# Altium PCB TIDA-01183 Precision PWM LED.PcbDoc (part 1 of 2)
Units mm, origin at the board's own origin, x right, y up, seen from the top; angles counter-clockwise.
Board outline 88 x 70 mm, 2 copper layers (Top Layer, Bottom Layer), stack 1.575 mm thick; 108 components, 41 nets, 240 pads, 138 vias.
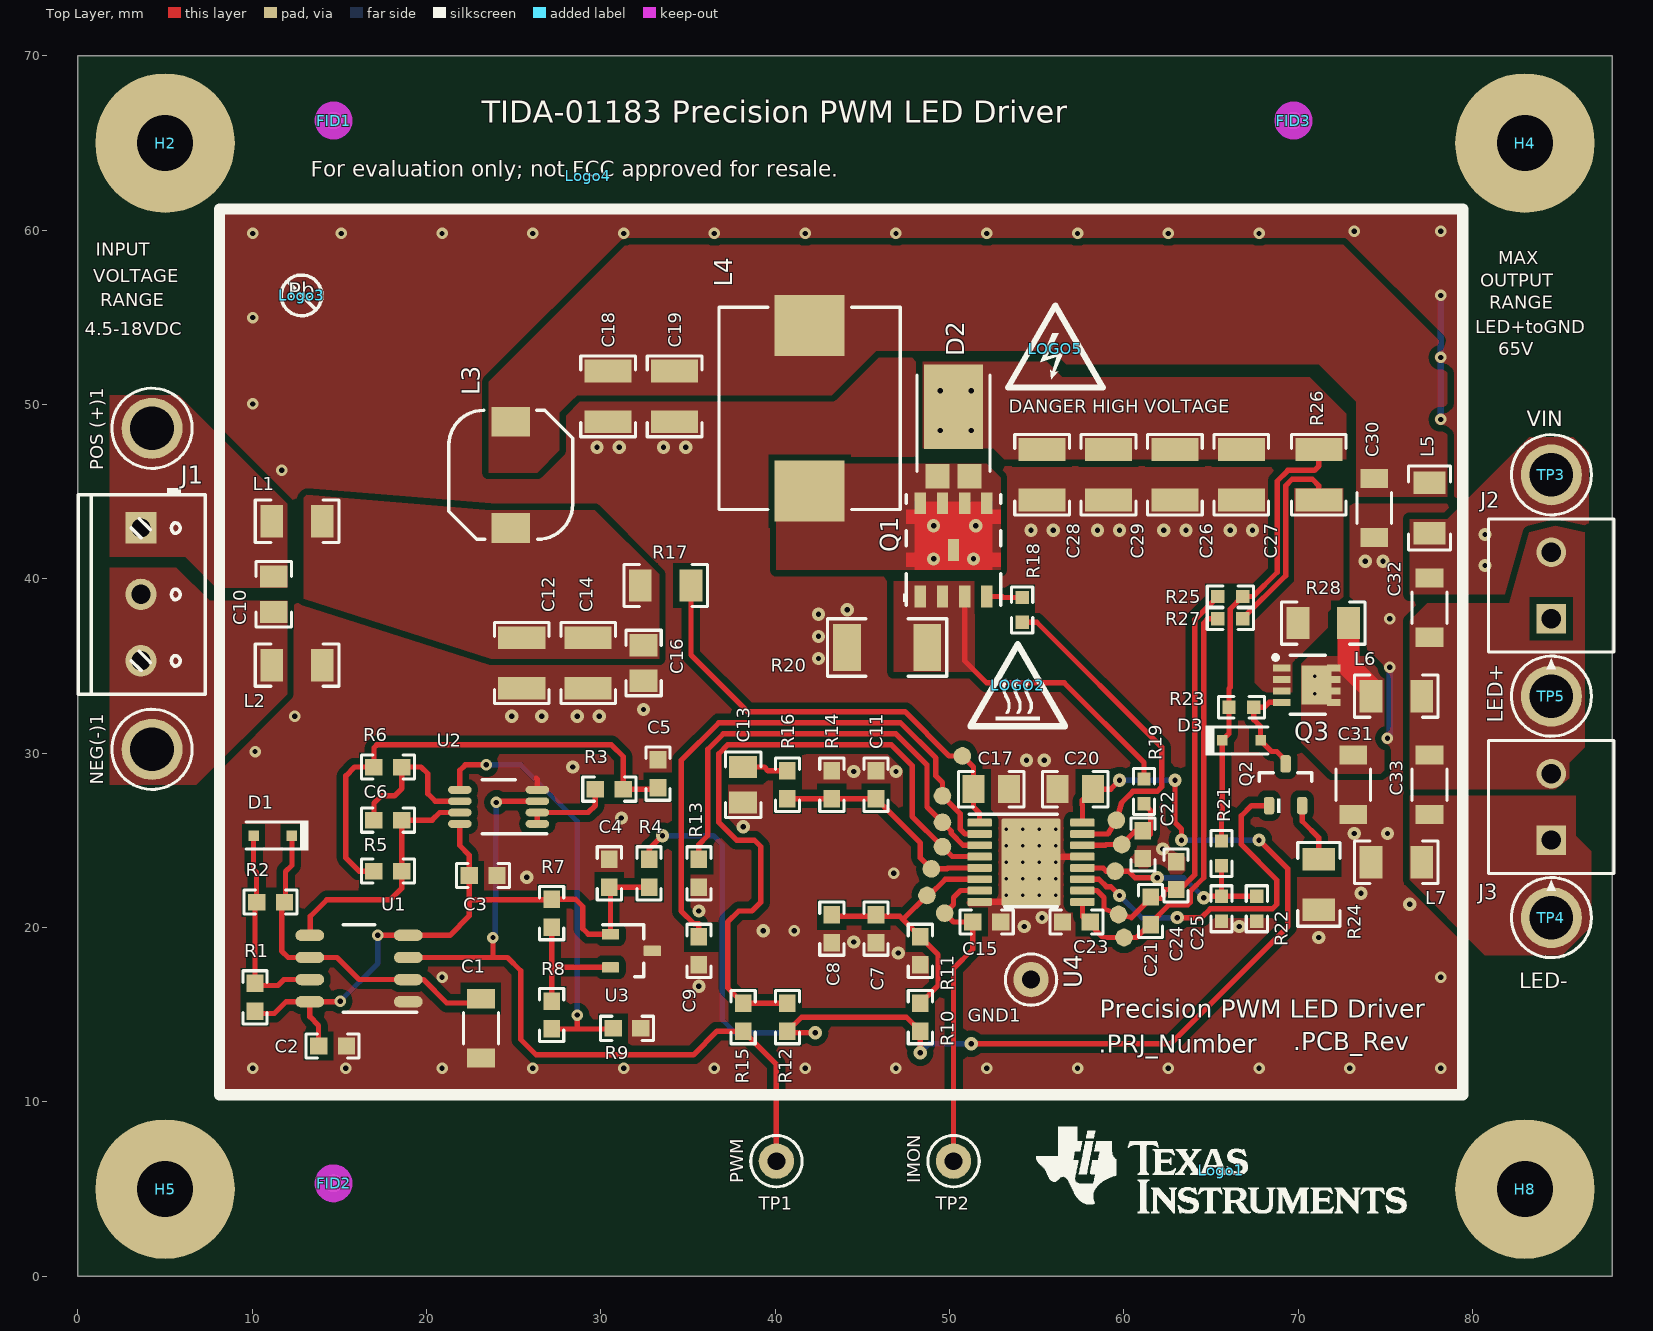
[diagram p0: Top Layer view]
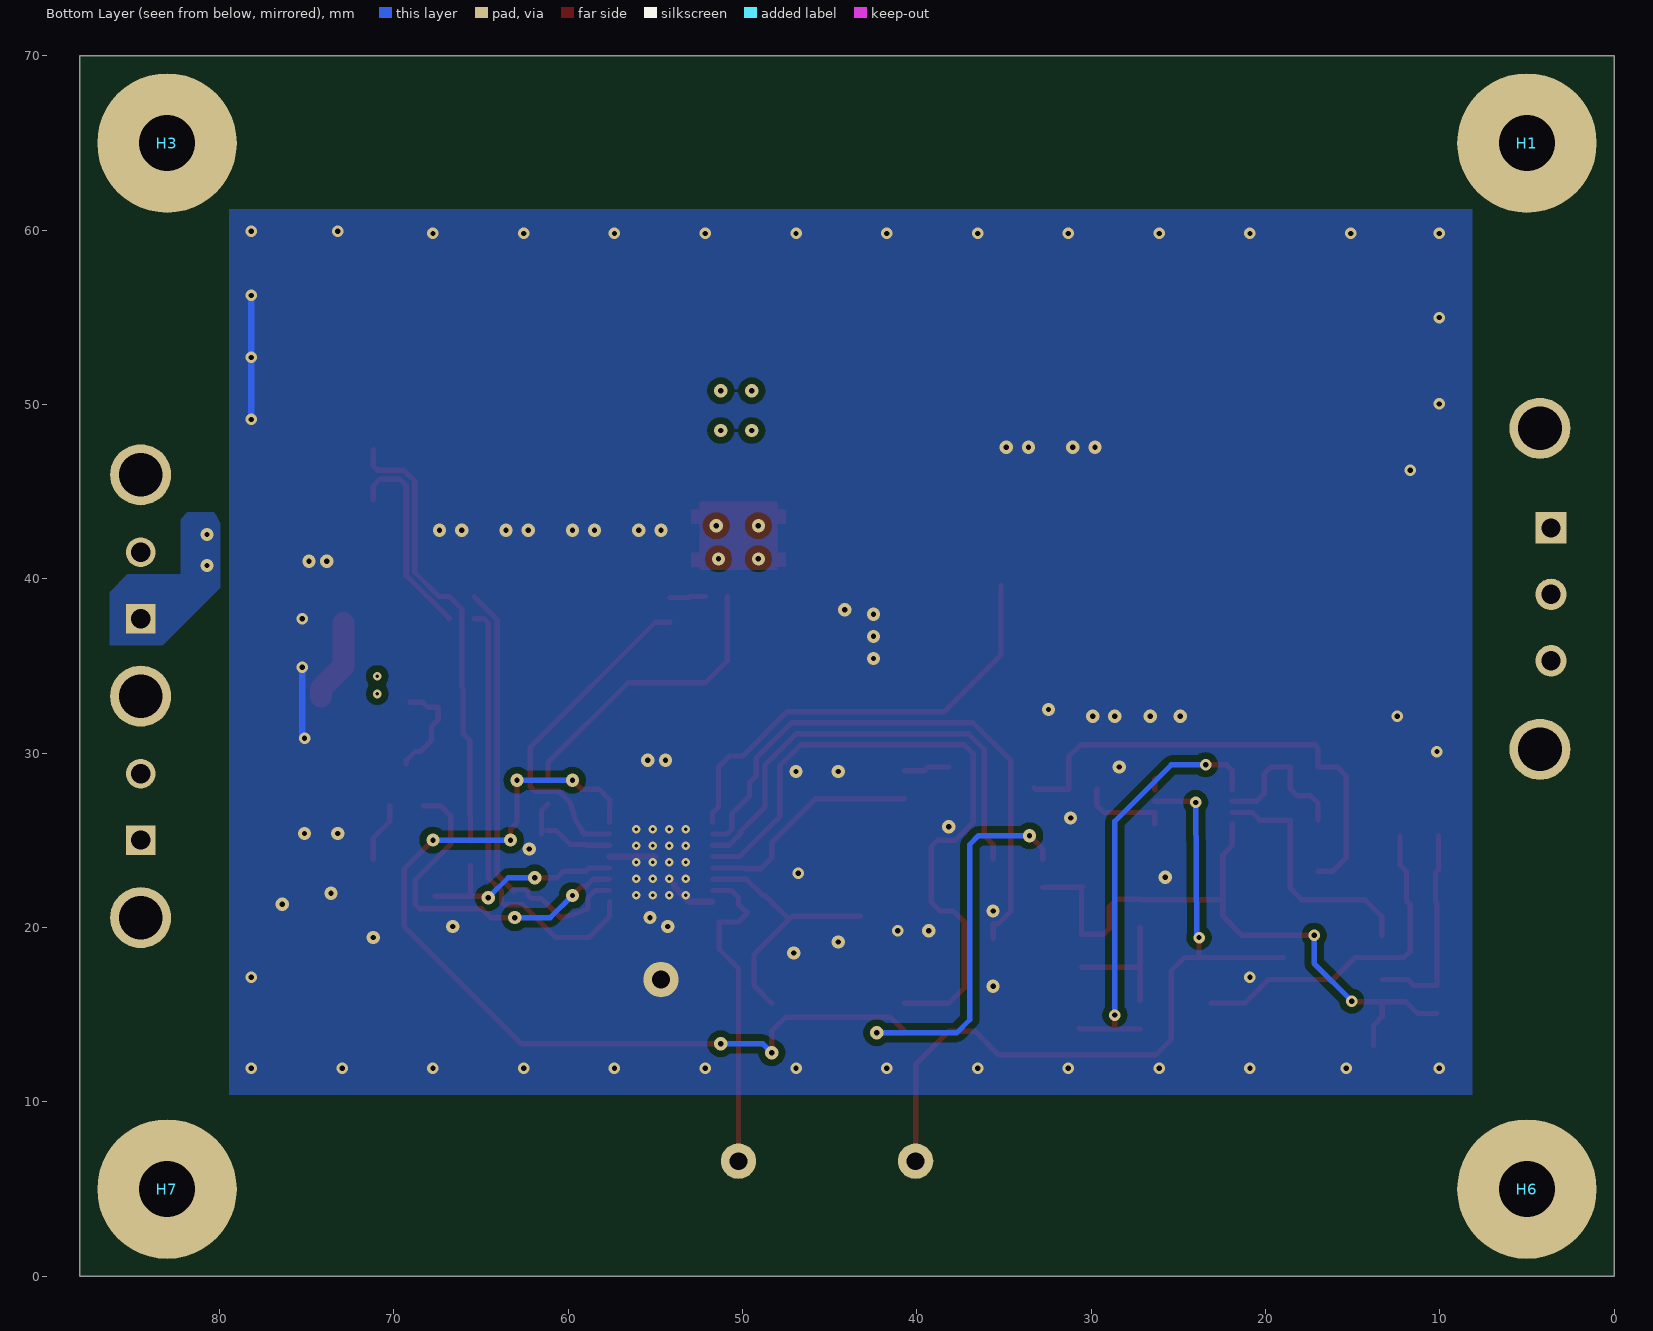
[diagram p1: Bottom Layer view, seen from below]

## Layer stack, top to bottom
Top Solder: solder mask 0.0102, Solder Resist, Dk 3.5
Top Layer: signal copper 0.0356
Dielectric1: core 1.5037, FR-4, Dk 4.8
Bottom Layer: signal copper 0.0356
Bottom Solder: solder mask 0.0102, Solder Resist, Dk 3.5

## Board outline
0,0 88,0 88,70 0,70
cut-out: -31.547,-42.774 -31.293,-42.774 -31.293,-42.52 -31.547,-42.52

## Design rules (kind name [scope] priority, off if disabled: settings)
AcuteAngle [All] p1: minimum=4.50000000000000E+0001 checktracksonly=FALSE
AssemblyTestPointUsage [All] p1 off: valid=2
AssemblyTestpoint [All] p1 off: testpointundercomponent=TRUE minsize=1.016 maxsize=2.54 preferedsize=1.524 minholesize=0 maxholesize=1.016 preferedholesize=0.813 testpointgrid=0.025 usegrid=TRUE gridtolerance=0 allowsidetop=TRUE allowsidebottom=TRUE
Clearance Clearance_BoardEdge_Poly [OnCopper and InPoly vs IsKeepOut] p1: gap=0.635
Clearance Clearance_BoardEdge [OnCopper and Not InComponentClass('Logo') and not InComponentClass('FiducialMark') and not InRegion(1000,500,4000,800) and Not IsKeepout vs IsKeepOut] p2: gap=0.635
Clearance Clearance_Poly [InPolygon] p3: gap=0.381
Clearance [All] p4: gap=0.178
ComponentClearance ComponentClearance_MountingHoles [InComponent('H1') or InComponent('H2')or InComponent('H4') or InComponent('H5') or InComponent('H8')] p1: gap=0 collisioncheckmode=3 verticalgap=0 showdistances=FALSE
ComponentClearance ComponentClearance_Logo [InComponentClass('Logo')] p2: gap=1.27 collisioncheckmode=3 verticalgap=0.254 showdistances=FALSE
ComponentClearance ComponentClearance_SmallPassives [HasFootprint('0201*') or HasFootprint('0402*') or HasFootprint('0508') or HasFootprint('0603*') or HasFootprint('0612') or HasFootprint('0805*') or HasFootprint('0815*') or HasFootprint('0830*') or HasFootprint('1206*') or HasFootprint('1210*') or HasFootprint('1808*') or HasFootprint('1812*') or HasFootprint('1825*') or HasFootprint('2010*') or HasFootprint('2220*') or HasFootprint('2225*') or HasFootprint('2512*') or HasFootprint('2728*') or HasFootprint('3518*') vs HasFootprint('0201*') or HasFootprint('0402*') or HasFootprint('0508') or HasFootprint('0603*') or HasFootprint('0612') or HasFootprint('0805*') or HasFootprint('0815*') or HasFootprint('0830*') or HasFootprint('1206*') or HasFootprint('1210*') or HasFootprint('1808*') or HasFootprint('1812*') or HasFootprint('1825*') or HasFootprint('2010*') or HasFootprint('2220*') or HasFootprint('2225*') or HasFootprint('2512*') or HasFootprint('2728*') or HasFootprint('3518*')] p3: gap=0.254 collisioncheckmode=3 verticalgap=0.254 showdistances=FALSE
ComponentClearance [All] p4: gap=0.381 collisioncheckmode=3 verticalgap=0.762 showdistances=FALSE
DiffPairsRouting [All] p1: maxlimit=2.54 minlimit=0.254 mostfreqgap=0.254 toplayer_minwidth=0.381 toplayer_maxwidth=0.381 toplayer_prefwidth=0.381 bottomlayer_minwidth=0.381 bottomlayer_maxwidth=0.381 bottomlayer_prefwidth=0.381 maxuncoupledlength=25.4
FabricationTestPointUsage TestPointUsage [All] p1 off: valid=2 allowmultiple=FALSE
FabricationTestpoint Testpoint [All] p1 off: side=3 testpointundercomponent=TRUE minsize=1.016 maxsize=2.54 preferedsize=1.524 minholesize=0 maxholesize=1.016 preferedholesize=0.813 testpointgrid=0.025 allowsidetop=TRUE allowsidebottom=TRUE usegrid=TRUE gridtolerance=0
FanoutControl Fanout_LCC [IsLCC] p1: bgadir=Out bgaviamode=Centered fanoutstyle=Auto fanoutdirection=Alternating viagrid=0.025 // Fanout_LCC (Default Rule)
FanoutControl Fanout_BGA [IsBGA] p2: bgadir=Out bgaviamode=Centered fanoutstyle=Auto fanoutdirection=Alternating viagrid=0.025 // Fanout_BGA (Default Rule)
FanoutControl Fanout_Default [All] p4: bgadir=Out bgaviamode=Centered fanoutstyle=Auto fanoutdirection=Alternating viagrid=0.025 // Fanout_Default (Default Rule)
FanoutControl Fanout_Small [(CompPinCount < 5)] p5: bgadir=Out bgaviamode=Centered fanoutstyle=Auto fanoutdirection=OutThenIn viagrid=0.025 // Fanout_Small (Default Rule)
HoleSize [All] p1: absolutevalues=TRUE maxlimit=6.375 minlimit=0.2 maxpercent=80.000 minpercent=20.000
MinimumAnnularRing MinimumAnnularRing_ThermalPadVias [IsVia and InAnyComponent] p1: minimumring=0.14
MinimumAnnularRing [All] p2: minimumring=0.14
MinimumSolderMaskSliver MinimumSolderMaskSliver_Logo [InComponentClass('Logo') vs InComponentClass('Logo')] p1: minsoldermaskwidth=0.018
MinimumSolderMaskSliver [All] p2: minsoldermaskwidth=0.1
PlaneConnect [All] p1: planeconnectstyle=Relief reliefexpansion=0.254 reliefentries=4 reliefconductorwidth=0.254 reliefairgap=0.254
PolygonConnect [All] p1: connectstyle=Direct reliefconductorwidth=0.254 reliefentries=4 polygonreliefangle="90 Angle" airgapwidth=0.254
RoutingVias ThermalPadVias [IsVia and InAnyComponent] p1: holewidth=0.2 width=0.66 viastyle="Through Hole" minholewidth=0.2 minwidth=0.5 maxholewidth=0.381 maxwidth=0.66
RoutingVias [All] p2: holewidth=0.406 width=0.864 viastyle="Through Hole" minholewidth=0.2 minwidth=0.66 maxholewidth=1.016 maxwidth=1.651
SilkToBoardRegionClearance [Not ((IsComment or IsDesignator) And (Hide <> 'False')) and not InRegion(1000,500,4000,800)] p1:
SilkToSilkClearance SilkToSilkClearance_Pb-FreeLogo [(HasFootprint('Pb-Free_Overlay_Medium') OR HasFootprint('Pb-Free_Overlay_Small')) vs (HasFootprint('Pb-Free_Overlay_Medium') OR HasFootprint('Pb-Free_Overlay_Small'))] p1: silktosilkclearance=0
SilkToSilkClearance [All] p2: silktosilkclearance=0.102
SilkToSolderMaskClearance SilkToSolderMaskClearance_PhxContact [(HasFootprint('PhoenixConact_1727010') OR HasFootprint('Phoenix_1727023'))] p1: minsilkscreentomaskgap=-0.025 clearancetoexposedcopper=TRUE
SilkToSolderMaskClearance SilkToSolderMaskClearance_Vias [IsVia] p2: minsilkscreentomaskgap=-0.025 clearancetoexposedcopper=TRUE
SilkToSolderMaskClearance [IsPad] p3: minsilkscreentomaskgap=0.127 clearancetoexposedcopper=TRUE
SilkToSolderMaskClearance "Silk to Solder Mask Opening" [All] p4: minsilkscreentomaskgap=0.102 clearancetoexposedcopper=FALSE
SolderMaskExpansion [All] p1: expansion=0.05
Width [All] p1: maxlimit=2.54 minlimit=0.178 preferedwidth=0.305 minimp=50.000000 maximp=50.000000 favimp=50.000000 checkconnectedcopper=TRUE
14 further rules are at their usual default settings.

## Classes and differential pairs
component class "TIDA-01183 Precision PWM LED_1": C1 C2 C3 C4 C5 C6 D1 R1 R2 R3 R4 R5 R6 R7 R8 R9 U1 U2 U3
component class "TIDA-01183 Precision PWM LED_2": C7 C8 C9 C10 C11 C12 C13 C14 C15 C16 C17 C18 C19 C20 C21 C22 C23 C24 C25 C26 C27 C28 C29 C30 C31 C32 C33 D2 D3 GND1 J1 J2 J3 L1 L2 L3 L4 L5 L6 L7 NEG(-) NEG(-)1 "POS (+)1" Q1 Q2 Q3 R10 R11 R12 R13 R14 R15 R16 R17 R18 R19 R20 R21 R22 R23 R24 R25 R26 R27 R28 TP1 TP2 TP3 TP4 TP5 U4
component class Logo: Logo1
component class "TIDA-01183 Precision PWM LED_Hardware": FID1 FID2 FID3 H1 H2 H3 H4 H5 H6 H7 H8 Logo1 LOGO2 Logo3 Logo4 LOGO5 ZZ1 ZZ2 ZZ3
component class FiducialMark: FID1 FID2 FID3
component class AssemblyNote: ZZ1 ZZ2 ZZ3
component class "Mounting Holes": H2 H4 H5 H8

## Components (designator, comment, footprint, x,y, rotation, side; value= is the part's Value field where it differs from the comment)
C1 "C3216C0G2A104J160AC" 1206_190 23.114,14.224 r270 top
C2 "0603YC104JAT2A" 0603 14.605,13.208 r0 top
C3 "GRM188R71C105KA12D" 0603 23.241,22.987 r180 top
C4 "GRM188R61C475KAAJ" 0603 30.48,23.114 r90 top
C5 "GRM188R71E474KA12D" 0603 33.274,28.829 r90 top
C6 "GRM188R71C103KA01D" 0603 17.78,26.162 r180 top
C7 "06033C104JAT2A" 0603 45.78,19.939 r270 top
C8 "06033C104JAT2A" 0603 43.24,19.939 r270 top
C9 "06033C104JAT2A" 0603 35.62,18.669 r270 top
C10 "C2012X7R2A104K125AA" 0805_HV 11.236,39.116 r270 top
C11 "GRM188R71E332KA01D" 0603 45.78,28.194 r90 top
C12 "C3225X7S2A475K200AE" 1210 25.46,35.179 r270 top
C13 "GRM216R71E333KA01D" 0805_HV 38.16,28.194 r90 top
C14 "C3225X7S2A475K200AE" 1210 29.27,35.179 r270 top
C15 "06035A100JAT2A" 0603 52.13,20.32 r0 top
C16 "C2012X7R2A104K125AA" 0805_HV 32.445,35.179 r270 top
C17 "C2012X7R2A104K125AA" 0805_HV 52.384,27.94 r180 top
C18 "C3225X7S2A475K200AE" 1210 30.413,50.472 r270 top
C19 "C3225X7S2A475K200AE" 1210 34.223,50.472 r270 top
C20 "C0805C225K4RACTU" 0805_HV 57.21,27.94 r180 top
C21 "GRM188R71H104KA93D" 0603 61.528,20.955 r270 top
C22 "GRM1885C2A102JA01D" 0603 61.087,24.765 r270 top
C23 "CGA3E2X7R2A103K080AA" 0603 57.277,20.32 r180 top
C24 "CGA3E2X7R2A103K080AA" 0603 62.992,22.987 r90 top
C25 "C1608C0G2A102J080AA" 0603_HV 65.592,21.082 r270 top
C26 "C3225X7S2A475K200AE" 1210 62.925,45.974 r90 top
C27 "C3225X7S2A475K200AE" 1210 66.735,45.974 r90 top
C28 "C3225X7S2A475K200AE" 1210 55.305,45.974 r90 top
C29 "C3225X7S2A475K200AE" 1210 59.115,45.974 r90 top
C30 "C3216X7R2A104K160AA" 1206_180 74.355,44.069 r270 top
C31 "C3216X7R2A104K160AA" 1206_180 73.152,28.194 r270 top
C32 "C3216X7R2A474K160AA" 1206_180 77.53,38.354 r270 top
C33 "C3216X7R2A104K160AA" 1206_180 77.53,28.194 r270 top
D1 "BAT165E6327HTSA1" SOD-323 11.176,25.273 r180 top
D2 "PDS3100Q-13" PowerDI5 50.225,47.879 r90 top
D3 "MMSZ5237BS-7-F" sod-323 66.735,30.734 r0 top
FID1 "Fiducial" Fiducial10-20 14.665,66.294 r0 top
FID2 "Fiducial" Fiducial10-20 14.665,5.334 r0 top
FID3 "Fiducial" Fiducial10-20 69.723,66.294 r0 top
GND1 "5001" Keystone5001 54.67,17.018 r0 top
H1 "1902C" Keystone_1902C 5.009,65 r180 bottom
H2 "NY PMS 440 0025 PH" "NY PMS 440 0025 PH" 5,65 r0 top
H3 "1902C" Keystone_1902C 83.009,65 r180 bottom
H4 "NY PMS 440 0025 PH" "NY PMS 440 0025 PH" 83,65 r0 top
H5 "NY PMS 440 0025 PH" "NY PMS 440 0025 PH" 5,5 r0 top
H6 "1902C" Keystone_1902C 5,5 r180 bottom
H7 "1902C" Keystone_1902C 83.009,5 r180 bottom
H8 "NY PMS 440 0025 PH" "NY PMS 440 0025 PH" 83,5 r0 top
J1 "1727023" Phoenix_1727023 3.616,39.116 r270 top
J2 "1727010" PhoenixConact_1727010 84.515,39.624 r90 top
J3 "1727010" PhoenixConact_1727010 84.515,26.924 r90 top
L1 "HI1206T161R-10" 1206 12.573,43.307 r0 top
L2 "HI1206T161R-10" 1206 12.573,35.052 r0 top
L3 "CLF7045T-3R3N" CLF7045 24.825,45.974 r90 top
L4 "IHLP4040DZER220M8A" IHLP-4040DZ 41.97,49.784 r270 top
L5 "MI1206K601R-10" 1206 77.53,44.069 r270 top
L6 "MI1206K601R-10" 1206 75.625,33.274 r0 top
L7 "MI1206K601R-10" 1206 75.625,23.749 r0 top
Logo1 "Texas Instruments" TI_Stacked_Overlay_Small 65.592,6.096 r0 top
LOGO2 "CAUTION HOT SURFACE" IEC_HotSurface_Small 53.908,33.909 r0 top
Logo3 "Pb-Free Symbol" Pb-Free_Overlay_Small 12.827,56.261 r0 top
Logo4 "FCC disclaimer" FCC_disclaimer 29.27,63.119 r0 top
LOGO5 "DANGER HIGH VOLTAGE" IEC_HighVoltage_Small 56.067,53.213 r0 top
NEG(-)1 "GND" Keystone1502-2 4.251,30.226 r180 top
"POS (+)1" "Suggest using a net name here" Keystone1502-2 4.251,48.641 r0 top
Q1 "STL8N10LF3" PowerFLAT5x6_R 50.225,41.664 r90 top
Q2 "DMN10H220L-7" SOT-23 69.275,28.194 r90 top
Q3 "SI7415DN-T1-GE3" PowerPAK_1212-8 70.545,33.909 r0 top
R1 "CRCW060310K0FKEA" 0603 10.16,16.002 r270 top
R2 "RC0603FR-0739KL" 0603 11.049,21.463 r180 top
R3 "RC0603FR-078K2L" 0603 30.48,27.94 r0 top
R4 "CRCW0603470RJNEA" 0603 32.766,23.114 r90 top
R5 "CRCW0603158KFKEA" 0603 17.78,23.241 r0 top
R6 "CRCW060334K0FKEA" 0603 17.78,29.21 r0 top
R7 "RG1608P-203-B-T5" 0603 27.178,20.828 r90 top
R8 "RG1608P-183-B-T5" 0603 27.178,14.986 r90 top
R9 "RG1608P-202-B-T5" 0603 31.496,14.224 r180 top
R10 "CRCW0603102KFKEA" 0603 48.32,14.859 r270 top
R11 "CRCW060311K8FKEA" 0603 48.32,18.669 r90 top
R12 "CRCW0603100KFKEA" 0603 40.7,14.859 r90 top
R13 "CRCW060320K0FKEA" 0603 35.62,23.114 r90 top
R14 "CRCW06034M99FKEA" 0603 43.24,28.194 r270 top
R15 "CRCW06031K00JNEA" 0603 38.16,14.859 r90 top
R16 "CRCW06031K43FKEA" 0603 40.7,28.194 r270 top
R17 "CRCW120610R0FKEA" 1206 33.715,39.624 r180 top
R18 "CRCW06030000Z0EA" 0603_HV 54.162,38.227 r90 top
R19 "CRCW0603100RFKEA" 0603_HV 61.147,27.813 r90 top
R20 "CSRN2010FK60L0" 2010 46.415,36.068 r0 top
R21 "CRCW0603487KFKEA" 0603_HV 65.592,24.257 r90 top
R22 "CRCW060310K0FKEA" 0603_HV 67.624,21.082 r90 top
R23 "CRCW06032K00FKEA" 0603_HV 66.735,32.639 r180 top
R24 "CRCW12061K00FKEA" 1206 71.18,22.479 r90 top
R25 "CRCW060310R0FKEA" 0603_HV 66.1,38.989 r0 top
R26 "MCR25JZHFLR160" 1210 71.18,45.974 r270 top
R27 "CRCW060310R0FKEA" 0603_HV 66.1,37.719 r0 top
R28 "CRCW12060000Z0EA" 1206 71.434,37.465 r180 top
TP1 "5003" Keystone5003 40.065,6.604 r0 top
TP2 "5003" Keystone5003 50.225,6.604 r0 top
TP3 "VIN" Keystone1502-2 84.515,45.974 r0 top
TP4 "LED-" Keystone1502-2 84.515,20.574 r0 top
TP5 "LED+" Keystone1502-2 84.515,33.274 r180 top
U1 "TLC555QDRQ1" D0008A_M 16.129,17.653 r180 top
U2 "OPA2377AIDGKR" DGK0008A_N 24.13,26.924 r180 top
U3 "TL431AQDBZRQ1" DBZ0003A_N 31.75,18.669 r0 top
U4 "TPS92691QPWPRQ1" PWP0016J_N 54.67,23.749 r0 top
ZZ1 "These assemblies are ESD sensitive, ESD precautions shall be observed." AssemblyNote 0.635,90.424 r0 top
ZZ2 "These assemblies must be clean and free from flux and all contaminants. Use of no clean flux is not acceptable." AssemblyNote 0.635,87.757 r0 top
ZZ3 "These assemblies must comply with workmanship standards IPC-A-610 Class 2, unless otherwise specified." AssemblyNote 0.635,85.09 r0 top

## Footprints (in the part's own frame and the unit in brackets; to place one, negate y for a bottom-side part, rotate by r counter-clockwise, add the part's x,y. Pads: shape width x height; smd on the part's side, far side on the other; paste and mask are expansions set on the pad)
0603 [mm] "0603 from SM-752 data"
  rect 1x0.95 smd: 1(-0.8,0) 2(0.8,0)
  silkscreen extent -1.52,-0.69 1.52,0.69, body extent -0.87,-0.47 0.87,0.47, height 1
0603_HV [mil] "Ernesto recommended land pattern.  26 mil between pads."
  rect 30x30 smd: 1(-28,0) 2(28,0)
  silkscreen extent -52,-24 52,24, body extent -34,-19 34,19, height 39
0805_HV [mil] "0805 with 30mil clearance between pads"
  rect 50x63 smd: 1(-40,0) 2(40,0)
  silkscreen extent -74,-40 74,40, body extent -43,-29 43,29, height 57
1206 [mm] "1206 from SM-752 data"
  rect 1.3x1.85 smd: 1(-1.45,0) 2(1.45,0)
  silkscreen extent -2.4,-1.21 2.4,1.21, body extent -1.7,-0.9 1.7,0.9, height 1.35
1206_180 [mm] "1206_180"
  rect 1.1x1.6 smd: 1(-1.7,0) 2(1.7,0)
  silkscreen extent -0.9,-1 0.9,1, body extent -1.75,-0.95 1.75,0.95, height 1.8
1206_190 [mm] "1206_190"
  rect 1.1x1.6 smd: 1(-1.7,0) 2(1.7,0)
  silkscreen extent -0.9,-1 0.9,1, body extent -1.75,-0.95 1.75,0.95, height 1.9
1210 [mm] "1210 from SM-752 data"
  rect 1.3x2.7 smd: 1(-1.45,0) 2(1.45,0)
  silkscreen extent -2.32,-1.57 2.32,1.57, body extent -1.7,-1.35 1.7,1.35, height 1.35
2010 [mm] "Chip Capacitor, Body 5.08x2.54mm, IPC Medium Density"
  rect 1.6x2.7 smd: 1(-2.3,0) 2(2.3,0)
  silkscreen extent -3.42,-1.65 3.42,1.65, body extent -2.73,-1.45 2.73,1.45, height 1.66
AssemblyNote [mm] "Assembly Note"
CLF7045 [mm] "TDK"
  rect 1.7x2.2 smd: 1(-3.05,0) 2(3.05,0)
  silkscreen extent -3.7,-3.55 3.7,3.55, body extent -3.7,-3.55 3.7,3.55, height 4.8
D0008A_M [mm] "SOIC, 8-Leads, Body 4.9x3.9mm, Pitch 1.27mm, IPC Low Density"
  oval 1.65x0.65 smd: 1(-2.825,1.905) 2(-2.825,0.635) 3(-2.825,-0.635) 4(-2.825,-1.905) 5(2.825,-1.905) 6(2.825,-0.635) 7(2.825,0.635) 8(2.825,1.905)
  silkscreen extent -3.3,-2.5 0.9,2.5, body extent -3,-2.45 3,2.45, height 1.63
DBZ0003A_N [mm] "SOT23, 3-Leads, Body 2.9x1.3mm, Pitch 0.95mm, Lead Span 2.4mm, IPC Medium Density"
  rrect17% 1x0.6 smd: 1(-1.2,0.95) 2(-1.2,-0.95) 3(1.2,0)
  silkscreen extent -1.65,-1.5 0.7,1.5, body extent -1.26,-1.46 1.26,1.46, height 0.98
DGK0008A_N [mm] "TSOP, 8-Leads, Body 3x3mm, Pitch 0.65mm, IPC Medium Density"
  oval 1.35x0.45 smd: 1(-2.225,0.975) 2(-2.225,0.325) 3(-2.225,-0.325) 4(-2.225,-0.975) 5(2.225,-0.975) 6(2.225,-0.325) 7(2.225,0.325) 8(2.225,0.975)
  silkscreen extent -2.75,-1.55 0.95,1.55, body extent -2.45,-1.5 2.45,1.5, height 0.96
FCC_disclaimer [mm]
Fiducial10-20 [mm]
  round 1 smd mask+0.5: 1(0,0)
  Top Layer keep-out circle w1.178: c0,0 r0.5
IEC_HighVoltage_Small [mm]
  silkscreen extent -2.72,-2.24 2.72,2.47
IEC_HotSurface_Small [mm]
  silkscreen extent -2.72,-2.36 2.72,2.35
IHLP-4040DZ [mm] "Vishay Dale recommended land pattern.  Document 34192 rev 04-Jul-08"
  rect 3.5x4 smd: 1(-4.75,0) 2(4.75,0)
  silkscreen extent -5.8,-5.2 5.8,5.2, body extent -5.75,-5.15 5.75,5.15, height 4
Keystone1502-2 [mm] "Double Turret"
  round 3.5 hole 2.5: 1(0,0)
  silkscreen extent -2.3,-2.3 2.3,2.3, body extent -1.6,-1.6 1.59,1.6, height 5.62
Keystone5001 [mil] "For Keystone 500x miniature loop terminals"
  round 80 hole 40: 1(0,0)
  silkscreen extent -58,-58 58,58, body extent -49,-49 49,49, height 182
Keystone5003 [mil] "For Keystone 500x miniature loop terminals"
  round 80 hole 40: 1(0,0)
  silkscreen extent -58,-58 58,58, body extent -49,-49 49,49, height 182
Keystone_1902C [mil] "Hex Standoff, 4-40 threaded, nylon"
  round 1 on Mech4: 0(0,0)
  body extent -145,-126 146,126, height 501
"NY PMS 440 0025 PH" [mm] "4-40 nylon screw and mounting hole"
  round 8 hole 3.2: 1(0,0)
  body extent -3.3,-3.3 3.3,3.3, height 2.69
Pb-Free_Overlay_Small [mm]
  silkscreen extent -1.16,-1.17 1.17,1.17
Phoenix_1727023 [mm] "Phoenix Contact"
  rect 1.8x1.8 hole 1.1: 1(-3.81,0)
  round 1.8 hole 1.1: 2(0,0) 3(3.81,0)
  silkscreen extent -6.1,-3.6 5.72,3.7, body extent -5.71,-3.6 5.72,3.7, height 8.5
PhoenixConact_1727010 [mm]
  rect 1.7x1.7 hole 1.1: 1(-1.905,0)
  round 1.7 hole 1.1: 2(1.905,0)
  silkscreen extent -4.8,-3.6 3.81,3.6, body extent -3.81,-3.6 3.81,3.7, height 8.52
PowerDI5 [mm] "Diodes Inc recommended land pattern, ap02001.pdf rev 60"
  rect 1.4x1.39 smd: 1(-1.991,0.92) 2(-1.991,-0.92)
  rect 4.86x3.36 smd: 3(1.991,0)
  silkscreen extent -1.7,-2.1 3.8,2.1, body extent -2.27,-2.03 4.33,2.03, height 1.17
PowerFLAT5x6_R [mm] "SMD, 8-Leads, Body 6.15x5.2mm, Pitch 1.27mm"
  rect 1.25x0.65 smd: 1(-2.675,1.905) 2(-2.675,0.635) 3(-2.675,-0.635) 4(-2.675,-1.905) 5(2.675,-1.905) 6(2.675,-0.635) 7(2.675,0.635) 8(2.675,1.905) 9(0,0)
  Top Layer region: -0.96,2.7 -0.96,2.225 -1.15,2.225 -1.15,-2.225 -0.96,-2.225 -0.96,-2.7 -0.16,-2.7 -0.16,-2.225 1.49,-2.225 1.49,-2.7 2.29,-2.7 2.29,-2.225 2.75,-2.225 2.75,2.225 2.29,2.225 2.29,2.7 1.49,2.7 1.49,2.225 -0.16,2.225 -0.16,2.7
  silkscreen extent -3.17,-2.7 3.17,2.9, body extent -3.17,-2.7 3.17,2.7, height 1.01
PowerPAK_1212-8 [mil] "Vishay PowerPAK 1212-8, Body 3.4x3.2mm (max), Pitch 0.65mm, IPC Medium Density"
  rect 39x16 smd mask+2.01: 1(-58.75,39) 2(-58.75,13) 3(-58.75,-13) 4(-58.75,-39)
  rect 30x16 smd mask+2.01: 5(58.75,-39) 6(58.75,-13) 7(58.75,13) 8(58.75,39)
  rect 68x88 smd mask+2.01: 9(19.75,0.61)
  silkscreen extent -78,-66 40,68, body extent -65,-65 65,65, height 43
PWP0016J_N [mm] "TSOP, 16-Leads, Body 5x4.4mm, Pitch 0.65mm, Exposed Pad, IPC Medium Density"
  rrect22% 1.4x0.45 smd: 1(-2.95,2.275) 2(-2.95,1.625) 3(-2.95,0.975) 4(-2.95,0.325) 5(-2.95,-0.325) 6(-2.95,-0.975) 7(-2.95,-1.625) 8(-2.95,-2.275) 9(2.95,-2.275) 10(2.95,-1.625) 11(2.95,-0.975) 12(2.95,-0.325) 13(2.95,0.325) 14(2.95,0.975) 15(2.95,1.625) 16(2.95,2.275)
  rrect6% 3.4x5 smd paste-1.7 mask-1.7: 17(0,0)
  rrect4% 2.46x3.55 on Top Paste: 17(0,0)
  rrect4% 2.46x3.55 on Top Solder: 17(0,0)
  silkscreen extent -3.55,-2.55 1.5,2.75, body extent -3.21,-2.5 3.21,2.5, height 1
SOD-323 [mm] "NXP recommended land pattern"
  rect 0.6x0.6 smd paste-0.05: 1(-1.1,0) 2(1.1,0)
  silkscreen extent -2.06,-0.86 1.53,0.86, body extent -1.3,-0.67 1.3,0.68, height 1.1
sod-323 [mm] "NXP recommended land pattern"
  rect 0.6x0.6 smd paste-0.05: 1(-1.1,0) 2(1.1,0)
  silkscreen extent -2.06,-0.86 1.53,0.86, body extent -1.3,-0.67 1.3,0.68, height 1.1
SOT-23 [mm] "SOT23, 3-Leads, Body 2.9x1.3mm, Pitch 0.95mm, Lead Span 2.5mm, IPC Medium Density"
  rrect50% 1x0.6 smd: 1(-1.2,0.95) 2(-1.2,-0.95) 3(1.2,0)
  silkscreen extent -1.62,-1.5 0.7,1.5, body extent -1.16,-1.45 1.21,1.45, height 1
TI_Stacked_Overlay_Small [mm]
  silkscreen extent -10.63,-2.49 10.63,2.49

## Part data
C1: "CAP, CERM, 0.1 µF, 100 V, +/- 5%, C0G/NP0, 1206_190"
C2: "CAP, CERM, 0.1 µF, 16 V, +/- 5%, X7R, 0603"
C3: "CAP, CERM, 1 µF, 16 V, +/- 10%, X7R, 0603"
C4: "CAP, CERM, 4.7 µF, 16 V, +/- 10%, X5R, 0603"
C5: "CAP, CERM, 0.47 µF, 25 V, +/- 10%, X7R, 0603"
C6: "CAP, CERM, 0.01 µF, 16 V, +/- 10%, X7R, 0603"
C7 C8 C9: "CAP, CERM, 0.1 µF, 25 V, +/- 5%, X7R, 0603"
C10 C16 C17: "CAP, CERM, 0.1 µF, 100 V, +/- 10%, X7R, 0805"
C11: "CAP, CERM, 3300 pF, 25 V, +/- 10%, X7R, 0603"
C12 C14 C18 C19 C26 C27 C28 C29: "CAP, CERM, 4.7 µF, 100 V, +/- 10%, X7S, 1210"
C13: "CAP, CERM, 0.033 µF, 25 V, +/- 10%, X7R, 0805"
C15: "CAP, CERM, 10 pF, 50 V, +/- 5%, C0G/NP0, 0603"
C20: "CAP, CERM, 2.2 µF, 16 V, +/- 10%, X7R, 0805"
C21: "CAP, CERM, 0.1 µF, 50 V, +/- 10%, X7R, 0603"
C22 C25: "CAP, CERM, 1000 pF, 100 V, +/- 5%, C0G/NP0, 0603"
C23 C24: "CAP, CERM, 0.01 µF, 100 V, +/- 10%, X7R, AEC-Q200 Grade 1, 0603"
C30 C31 C33: "CAP, CERM, 0.1 µF, 100 V, +/- 10%, X7R, 1206"
C32: "CAP, CERM, 0.47 µF, 100 V, +/- 10%, X7R, 1206"
D1: "Diode, Schottky, 40 V, 0.75 A, AEC-Q101, SOD-323"
D2: "Diode, Schottky, 100 V, 3 A, AEC-Q101, PowerDI5"
D3: "Diode, Zener, 8.2 V, 200 mW, SOD-323"
FID1 FID2 FID3: "Fiducial mark.  There is nothing to buy or mount."
GND1: "Test Point, Miniature, Black, TH"
H1 H3 H6 H7: "Standoff, Hex, 0.5\"L #4-40 Nylon"
H2 H4 H5 H8: "Machine Screw, Round, #4-40 x 1/4, Nylon, Philips panhead"
J1: "Terminal Block Receptacle, 3x1, 3.81mm, R/A, TH"
J2 J3: "Conn Term Block, 2POS, 3.81mm, TH"
L1 L2: "Ferrite Bead, 160 ohm @ 100 MHz, 6 A, 1206"
L3: "Inductor, Shielded, Ferrite, 3.3 µH, 5 A, 0.0213 ohm, SMD"
L4: "Inductor, Shielded Drum Core, Powdered Iron, 22 µH, 4.1 A, 0.0705 ohm, AEC-Q200 Grade 0, SMD"
L5 L6 L7: "Ferrite Bead, 600 ohm @ 100 MHz, 1.5 A, 1206"
Logo1: library part TI_Logo, "Texas Instrument Corporate Signature"
LOGO2: library part IEC_HotSurface, "IEC 61010-1 Hot Surface Warning"
Logo3: library part Pb-Free
Logo4: library part FCC_disclaimer, "FCC_disclaimer"
LOGO5: library part IEC_HighVoltage, "IEC 61010-1 High Voltage Warning"
NEG(-)1 "POS (+)1" TP3 TP4 TP5: library part 1502-2, "Terminal, Turret, TH, Double"
Q1: "MOSFET, N-CH, 100 V, 20 A, AEC-Q101, 8-PowerVDFN"
Q2: "MOSFET, N-CH, 100 V, 1.4 A, SOT-23"
Q3: "MOSFET, P-CH, -60 V, -3.6 A, PowerPAK 1212"
R1 R22: "RES, 10.0 k, 1%, 0.1 W, 0603"
R2: "RES, 39.0 k, 1%, 0.1 W, 0603"
R3: "RES, 8.20 k, 1%, 0.1 W, 0603"
R4: "RES, 470, 5%, 0.1 W, 0603"
R5: "RES, 158 k, 1%, 0.1 W, 0603"
R6: "RES, 34.0 k, 1%, 0.1 W, 0603"
R7: "RES, 20.0 k, 0.1%, 0.1 W, 0603"
R8: "RES, 18.0 k, 0.1%, 0.1 W, 0603"
R9: "RES, 2.00 k, 0.1%, 0.1 W, 0603"
R10: "RES, 102 k, 1%, 0.1 W, 0603"
R11: "RES, 11.8 k, 1%, 0.1 W, 0603"
R12: "RES, 100 k, 1%, 0.1 W, 0603"
R13: "RES, 20.0 k, 1%, 0.1 W, 0603"
R14: "RES, 4.99 M, 1%, 0.1 W, 0603"
R15: "RES, 1.0 k, 5%, 0.1 W, 0603"
R16: "RES, 1.43 k, 1%, 0.1 W, 0603"
R17: "RES, 10.0, 1%, 0.25 W, 1206"
R18: "RES, 0, 5%, 0.1 W, 0603"
R19: "RES, 100, 1%, 0.1 W, 0603"
R20: "RES, 0.06, 1%, 1 W, 2010"
R21: "RES, 487 k, 1%, 0.1 W, 0603"
R23: "RES, 2.00 k, 1%, 0.1 W, 0603"
R24: "RES, 1.00 k, 1%, 0.25 W, 1206"
R25 R27: "RES, 10.0, 1%, 0.1 W, 0603"
R26: "RES, 0.16, 1%, 0.5 W, 1210"
R28: "RES, 0, 5%, 0.25 W, 1206"
TP1 TP2: "Test Point, Miniature, Orange, TH"
U1: "LinCMOS Timer, D0008A"
U2: "Low-Cost, Low Noise, 5 MHz CMOS Operational Amplifier, 2.2 to 5.5 V, -40 to 125 degC, 8-pin SOP (DGK0008A), Green (RoHS & no Sb/Br)"
U3: "Automotive Catalog Adjustable Precision Shunt Regulator, 34 ppm / degC, 100 mA, -40 to 125 degC, 3-pin SOT-23 (DBZ), Green (RoHS & no Sb/Br)"
U4: "Multi-Topology LED Driver with Rail-to-Rail Current Sense Amplifier, PWP0016J"
ZZ1 ZZ2 ZZ3: library part AssemblyNote

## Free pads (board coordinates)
  round 1.016 smd: 1(48.701,21.844) 1(48.955,23.368) 1(49.59,24.638) 1(49.59,26.035) 1(49.59,27.559) 1(49.717,20.828) 1(50.733,29.845) 1(59.496,23.241) 1(59.563,26.162) 1(59.69,20.752) 1(59.877,24.765) 1(60.004,19.431)

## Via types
v1: diameter 0.762, hole 0.305, Top Layer to Bottom Layer, tented both sides, 66 vias
v2: diameter 0.66, hole 0.305, Top Layer to Bottom Layer, tented both sides, 49 vias
v3: diameter 0.5, hole 0.2, Top Layer to Bottom Layer, tented both sides, 14 vias
v4: diameter 0.5, hole 0.2, Top Layer to Bottom Layer, 8 vias
v5: diameter 0.762/0.762 (per signal layer), hole 0.305, Top Layer to Bottom Layer, tented both sides, 1 vias

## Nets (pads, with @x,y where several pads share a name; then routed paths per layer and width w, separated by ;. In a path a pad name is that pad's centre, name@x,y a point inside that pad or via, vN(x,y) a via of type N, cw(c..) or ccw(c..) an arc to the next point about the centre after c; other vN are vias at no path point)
GND: C1.2 C2.2 C3.1 C4.2 C5.2 C7.2 C8.2 C9.2 C11.2 C12.2 C13.1 C14.2 C15.2 C16.2 C17.1 C18.2 C19.2 C20.2 C22.2 C23.2 C24.2 C25.2 C26.1 C27.1 C28.1 C29.1 C30.2 C31.2 GND1.1 L2.2 L7.1 R9.1 R11.1 R13.1 R14.1 R20.1 R22.1 R24.1 U1.1 U2.4 U3.3 U4.8 U4.13 U4.17@54.67,23.749 | length 17.2
  Top Layer w0.305: 26.289,28.575 26.355,28.509 U2.4@26.355,27.899
  Top Layer w0.381: U4.8@51.72,21.474 53.03,21.474 53.908,22.352 U4.17@53.908,22.479 ; U4.17@54.995,24.074 U4.13@57.62,24.074
  Bottom Layer w0.381: v2(75.117,30.861) 75.244,30.988 v2(75.244,34.925) ; v2(78.165,49.149) v2(78.165,56.261)
  other v1: 35.62,16.637 47.05,18.542 44.51,19.177 71.18,19.431 39.303,19.812 54.289,20.066 66.608,20.066 55.305,20.574 35.62,20.955 76.387,21.336 73.593,21.971 25.747,22.896 62.23,24.511 73.212,25.4 75.117,25.4 38.16,25.781 31.175,26.289 44.51,28.956 46.923,28.956 54.416,29.591 55.432,29.591 24.892,32.131 26.603,32.131 28.635,32.131 29.905,32.131 32.445,32.512 42.478,35.433 42.478,36.703 42.478,37.973 44.129,38.227 73.847,41.021 74.863,41.021 54.67,42.799 55.94,42.799 58.48,42.799 59.75,42.799 62.29,42.799 63.56,42.799 66.1,42.799 67.37,42.799 29.778,47.551 31.048,47.551 33.588,47.551 34.858,47.551
  other v2: 10.033,11.938 15.367,11.938 20.888,11.938 26.095,11.938 31.302,11.938 36.509,11.938 41.716,11.938 46.923,11.938 52.13,11.938 57.337,11.938 62.544,11.938 67.751,11.938 72.958,11.938 78.165,11.938 20.888,17.145 78.165,17.145 41.081,19.812 46.796,23.114 10.16,30.099 12.446,32.131 75.244,37.719 11.684,46.228 10.033,50.038 78.165,52.705 10.033,54.991 10.033,59.817 15.113,59.817 20.888,59.817 26.095,59.817 31.302,59.817 36.509,59.817 41.716,59.817 46.923,59.817 52.13,59.817 57.337,59.817 62.544,59.817 67.751,59.817 73.212,59.944 78.165,59.944
  other v3: 53.245,21.849 54.195,21.849 55.145,21.849 56.095,21.849 53.245,22.799 56.095,22.799 53.245,23.749 56.095,23.749 53.245,24.699 56.095,24.699 53.245,25.649 54.195,25.649 55.145,25.649 56.095,25.649
  other v4: 54.195,22.799 55.145,22.799 54.195,23.749 55.145,23.749 54.195,24.699 55.145,24.699
  other v5: 28.381,29.21
IADJ: C7.1 C8.1 pad.1@48.701,21.844 R10.1 R11.2 U4.6 | length 15.6
  Top Layer w0.305: C8.1@43.24,20.65 45.78,20.65 47.139,20.65 47.304,20.485 ; R10.1@48.32,15.659 49.336,16.675 49.336,18.453 R11.2@48.32,19.469 47.304,20.485 ; U4.6@51.72,22.774 49.758,22.774 48.828,21.844 pad.1@48.701,21.844 47.342,20.485 47.304,20.485
IMON: C15.1 pad.1@49.717,20.828 TP2.1 U4.7 | length 18.8
  Top Layer w0.305: TP2.1@50.225,6.604 50.225,17.653 51.33,18.758 C15.1@51.33,20.32 50.225,20.32 pad.1@49.717,20.828 50.225,21.336 50.225,21.717 50.632,22.124 U4.7@51.72,22.124
NetC1_1: C1.1 D1.1 R2.1 U1.2 U1.6 | length 19.5
  Top Layer w0.305: D1.1@12.276,25.273 12.276,23.579 11.913,23.216 11.913,21.527 R2.1@11.849,21.463 11.684,21.298 11.684,18.669 12.065,18.288 U1.6@13.304,18.288 14.859,18.288 16.129,17.018 U1.2@18.954,17.018 19.812,17.018 21.156,15.674 C1.1@23.114,15.674
NetC5_1: C5.1 R3.2 R5.1 R6.1 | length 28.1
  Top Layer w0.305: R5.1@16.98,23.241 16.129,23.241 15.367,24.003 15.367,28.702 15.875,29.21 R6.1@16.98,29.21 16.98,30.315 17.145,30.48 30.607,30.48 31.28,29.807 R3.2@31.28,27.94 33.185,27.94 C5.1@33.274,28.029
NetC6_1: C6.1 R5.2 U1.5 U2.7 | length 14.4
  Top Layer w0.305: U1.5@13.304,19.558 13.335,19.589 13.335,20.653 14.272,21.59 17.907,21.59 18.58,22.263 R5.2@18.58,23.241 C6.1@18.58,26.162 20.32,26.162 20.757,26.599 U2.7@21.905,26.599
NetC6_2: C6.2 R6.2 U2.6 | length 9
  Top Layer w0.305: C6.2@16.98,26.162 16.98,27.14 17.399,27.559 18.161,27.559 18.58,27.978 R6.2@18.58,29.21 19.685,29.21 20.066,28.829 20.066,27.686 20.503,27.249 U2.6@21.905,27.249
NetC10_1: "POS (+)1.1" C10.1 J1.1 L1.1
NetC10_2: C10.2 J1.2 J1.3 L2.1 NEG(-)1.1
NetC11_1: C11.1 pad.1@48.955,23.368 R14.2 R16.2 U4.5 | length 13.2
  Top Layer w0.305: R16.2@40.7,27.394 R14.2@43.24,27.394 C11.1@45.78,27.394 48.32,24.854 48.32,24.003 pad.1@48.955,23.368 49.844,23.368 49.9,23.424 U4.5@51.72,23.424
NetC12_1: C12.1 C14.1 C16.1 L1.2 L3.1 R17.2
NetC13_2: C13.2 R16.1 | length 2.6
  Top Layer w0.305: C13.2@38.16,29.21 39.379,29.21 39.595,28.994 R16.1@40.7,28.994
NetC17_2: C17.2 pad.1@50.733,29.845 R17.1 U4.1 | length 26.2
  Top Layer w0.305: R17.1@35.165,39.624 35.165,35.634 38.414,32.385 47.431,32.385 49.971,29.845 pad.1@50.733,29.845 51.368,29.21 C17.2@51.368,27.94 51.368,26.924 51.72,26.572 U4.1@51.72,26.024
NetC18_1: C18.1 C19.1 C30.1 L3.2 L4.1 L5.1
NetC21_1: C21.1 C24.1 pad.1@59.69,20.752 R25.1 U4.10 | length 24.9
  Top Layer w0.305: U4.10@57.62,22.124 58.454,22.124 58.861,21.717 58.861,21.082 pad.1@59.69,20.752 60.436,20.574 61.528,21.666 62.112,21.666 62.299,21.853 62.299,22.123 62.363,22.187 C24.1@62.992,22.187 ; C24.1@63.105,22.074 64.068,23.038 64.068,37.668 R25.1@65.389,38.989
NetC21_2: C21.2 C23.1 pad.1@60.004,19.431 R27.1 U4.9 | length 25.6
  Top Layer w0.305: U4.9@57.62,21.474 57.62,20.621 57.921,20.32 58.81,19.431 pad.1@60.004,19.431 60.715,19.431 61.528,20.244 62.595,21.311 63.662,21.311 63.814,21.463 63.814,22.098 64.576,22.86 64.576,37.465 64.83,37.719 R27.1@65.389,37.719
NetC22_1: C22.1 pad.1@59.877,24.765 R19.1 U4.14 | length 5.9
  Top Layer w0.305: U4.14@57.62,24.724 58.947,24.724 58.988,24.765 pad.1@59.877,24.765 60.677,25.565 C22.1@61.214,25.565 ; R19.1@61.147,27.102 61.528,26.721 C22.1@61.528,25.349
